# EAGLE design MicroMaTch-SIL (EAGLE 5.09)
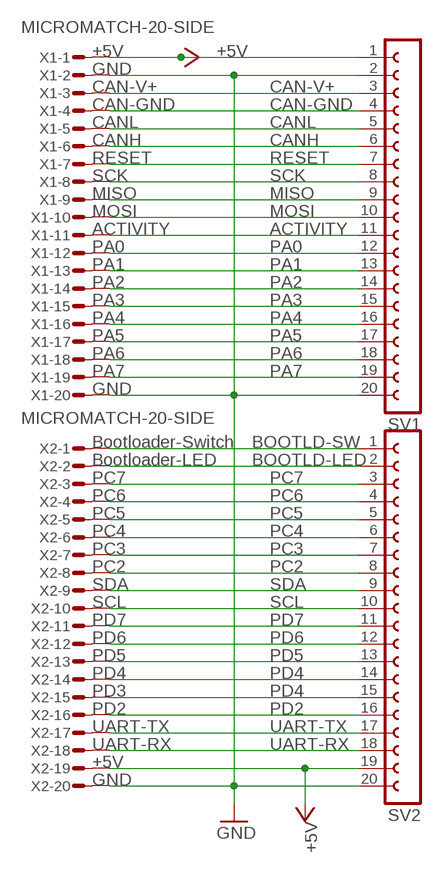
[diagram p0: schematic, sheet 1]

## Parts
SV1  FE20-1  [FE20]
SV2  FE20-1  [FE20]
X1  MICROMATCH-20-SIDE  [MICROMATCH-20-SIDE]
X2  MICROMATCH-20-SIDE  [MICROMATCH-20-SIDE]

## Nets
+5V: SV1.1 SV2.19 X1.1 X2.19
ACTIVITY: SV1.11 X1.11
BOOTLD-LED: SV2.2 X2.2
BOOTLD-SW: SV2.1 X2.1
CAN-GND: SV1.4 X1.4
CAN-V+: SV1.3 X1.3
CANH: SV1.6 X1.6
CANL: SV1.5 X1.5
GND: SV1.2 SV1.20 SV2.20 X1.2 X1.20 X2.20
MISO: SV1.9 X1.9
MOSI: SV1.10 X1.10
PA0: SV1.12 X1.12
PA1: SV1.13 X1.13
PA2: SV1.14 X1.14
PA3: SV1.15 X1.15
PA4: SV1.16 X1.16
PA5: SV1.17 X1.17
PA6: SV1.18 X1.18
PA7: SV1.19 X1.19
PC2: SV2.8 X2.8
PC3: SV2.7 X2.7
PC4: SV2.6 X2.6
PC5: SV2.5 X2.5
PC6: SV2.4 X2.4
PC7: SV2.3 X2.3
PD2: SV2.16 X2.16
PD3: SV2.15 X2.15
PD4: SV2.14 X2.14
PD5: SV2.13 X2.13
PD6: SV2.12 X2.12
PD7: SV2.11 X2.11
RESET: SV1.7 X1.7
SCK: SV1.8 X1.8
SCL: SV2.10 X2.10
SDA: SV2.9 X2.9
UART-RX: SV2.18 X2.18
UART-TX: SV2.17 X2.17

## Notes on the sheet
- +5V
- GND
- CAN-V+
- CAN-GND
- CANL
- CANH
- RESET | RESET
- SCK
- MISO
- MOSI
- ACTIVITY
- PA0
- PA1
- PA2
- PA3
- PA4
- PA5
- PA6
- PA7
- GND
- Bootloader-Switch
- Bootloader-LED
- PC7
- PC6
- PC5
- PC4
- PC3
- PC2
- SDA
- SCL
- PD7
- PD6
- PD5
- PD4
- PD3
- PD2
- UART-TX
- UART-RX
- +5V
- GND

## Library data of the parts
SV1 SV2 = con-lsta:FE20-1: FEMALE HEADER
X1 X2 = apbteam_con-amp-micromatch:MICROMATCH-20: Micro-MaTch 20 Straight connector: Suited for both, female and male.

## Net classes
0 default: width 0.15 mm
1 Power: width 0.5 mm

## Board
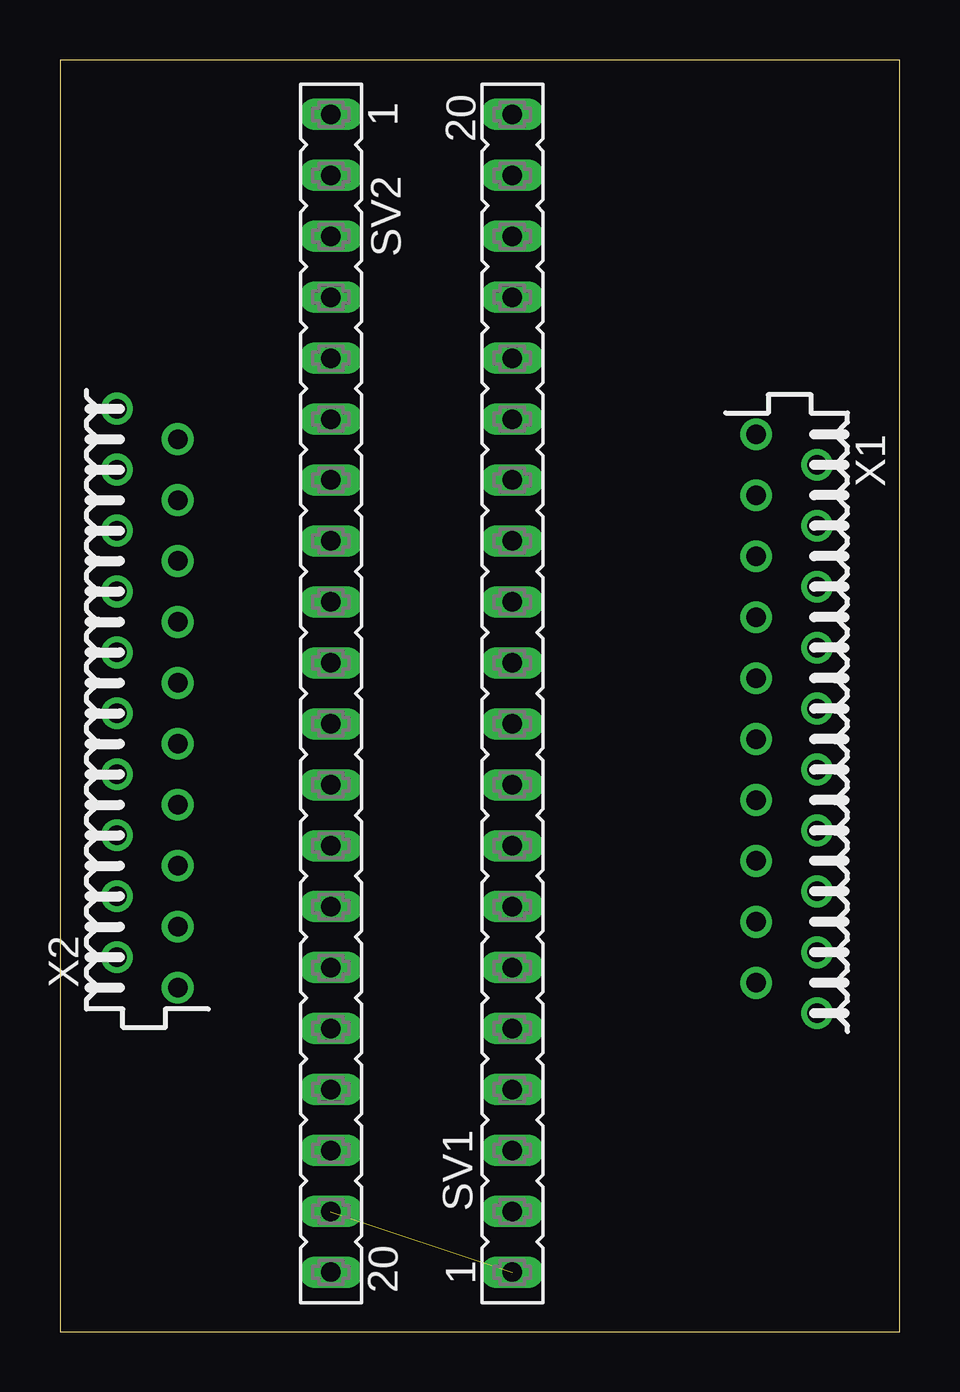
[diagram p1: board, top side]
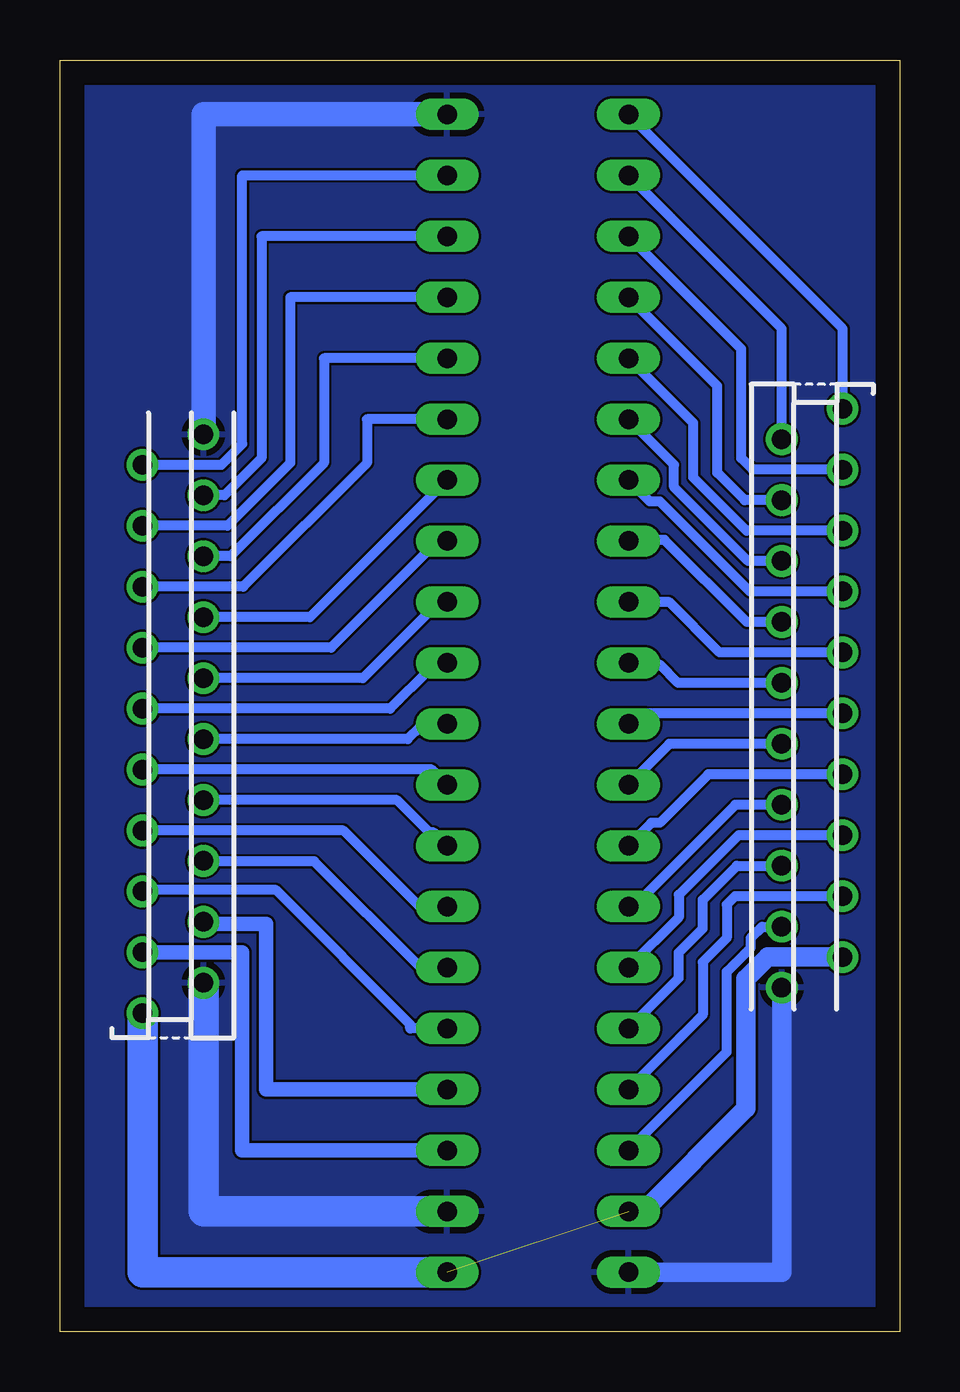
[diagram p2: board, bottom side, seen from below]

Size 35 x 53 mm. Coordinates in mm from the lower left corner, seen from the top.
Outline: 0,0 35,0 35,53 0,53 0,0
Copper layers (1*16): Top 0.035mm / dielectric 1.5mm / Bottom 0.035mm
Design rules "default *": minimum track width 0.2mm, minimum drill 0.2mm, track to track 0.1mm, track to pad 0.1mm, pad to pad 0.1mm, via to via 0.1mm, smd to smd 0.1mm, copper to edge 40mil, drill to drill 8mil, minimum pad ring 10mil, minimum via ring 8mil, stop-mask expansion 4mil, vias tented up to drill 0mil, thermal gap 10mil

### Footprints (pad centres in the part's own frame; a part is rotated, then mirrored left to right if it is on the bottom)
FE20 = drill 0.813 long: 1 -24.13,0; 2 -21.59,0; 3 -19.05,0; 4 -16.51,0; 5 -13.97,0; 6 -11.43,0; 7 -8.89,0; 8 -6.35,0; 9 -3.81,0; 10 -1.27,0; 11 1.27,0; 12 3.81,0; 13 6.35,0; 14 8.89,0; 15 11.43,0; 16 13.97,0; 17 16.51,0; 18 19.05,0; 19 21.59,0; 20 24.13,0
MICROMATCH-20-SIDE = drill 0.813 round: 1 12.065,1.27; 2 10.795,-1.27; 3 9.525,1.27; 4 8.255,-1.27; 5 6.985,1.27; 6 5.715,-1.27; 7 4.445,1.27; 8 3.175,-1.27; 9 1.905,1.27; 10 0.635,-1.27; 11 -0.635,1.27; 12 -1.905,-1.27; 13 -3.175,1.27; 14 -4.445,-1.27; 15 -5.715,1.27; 16 -6.985,-1.27; 17 -8.255,1.27; 18 -9.525,-1.27; 19 -10.795,1.27; 20 -12.065,-1.27

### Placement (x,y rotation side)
SV1  18.86,26.6 90 top
SV2  11.3,26.6 270 top
X1  30.29,25.33 270 top
X2  3.64,26.4 90 top

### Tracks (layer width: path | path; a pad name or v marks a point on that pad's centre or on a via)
+5V  (1 unrouted)
  Bottom 0.813: X2.19 5.5,15.61 6.4,14.7 6.4,9.3 10.7,5 SV2.19
  Bottom 1.27: X1.1 31.56,2.47 SV1.1
ACTIVITY
  Bottom 0.406: X1.11 21.23,25.96 19.6,27.6 19.13,27.6 SV1.11
BOOTLD-LED
  Bottom 0.406: X2.2 4.91,41.8 SV2.2
BOOTLD-SW
  Bottom 0.406: X2.1 2.37,41.8 SV2.1
CAN-GND
  Bottom 0.61: X1.4 29.02,17 26.4,17 26.4,10.09 SV1.4
CAN-V+
  Bottom 0.61: X1.3 27.4,15.8 27.4,7.55 SV1.3
CANH
  Bottom 0.406: X1.6 24.4,19.6 20,15.2 18.89,15.2 SV1.6
CANL
  Bottom 0.406: X1.5 31.56,18.4 26,18.4 20.4,12.8 20.4,12.63 SV1.5
GND
  Bottom 0.813: X2.20 4.91,2.47 SV2.20
  Bottom 1.016: X1.20 29.02,50.73 SV1.20
  Bottom 1.27: X1.2 29.02,5.01 SV1.2
  pour Bottom (isolate 0.1): 0,52.8 0,0 35,0 35,53 0,53
MISO
  Bottom 0.406: X1.9 19.5,23.42 SV1.9
MOSI
  Bottom 0.406: X1.10 20.5,24.7 20,25.2 18.99,25.2 SV1.10
PA0
  Bottom 0.406: X1.12 22.36,27.23 19.4,30.2 19.07,30.2 SV1.12
PA1
  Bottom 0.406: X1.13 23.7,28.5 19.4,32.8 19.01,32.8 SV1.13
PA2
  Bottom 0.406: X1.14 24.57,29.77 SV1.14
PA3
  Bottom 0.406: X1.15 27.36,31.04 22.2,36.2 22.2,38.03 SV1.15
PA4
  Bottom 0.406: X1.16 27.89,32.31 24,36.2 24,40.57 SV1.16
PA5
  Bottom 0.406: X1.17 28.02,33.59 25.4,36.2 25.4,43.11 SV1.17
PA6
  Bottom 0.406: X1.18 28.14,34.85 26.6,36.4 26.6,45.65 SV1.18
PA7
  Bottom 0.406: X1.19 28.27,36.12 27.4,37 27.4,48.19 SV1.19
PC2
  Bottom 0.406: X2.8 6.38,29.57 9.8,33 11.25,33 SV2.8
PC3
  Bottom 0.406: X2.7 6.25,30.84 10,34.6 10.41,34.6 SV2.7
PC4
  Bottom 0.406: X2.6 6.32,32.12 9.4,35.2 9.4,36.13 SV2.6
PC5
  Bottom 0.406: X2.5 6.38,33.38 8.6,35.6 8.6,37.87 SV2.5
PC6
  Bottom 0.406: X2.4 6.46,34.66 7.6,35.8 7.6,39.41 SV2.4
PC7
  Bottom 0.406: SV2.3 6.6,40.95 6.6,36.4 6.12,35.92 X2.3
PD2
  Bottom 0.406: X2.16 6.79,19.41 8.2,18 8.2,16.8 9.2,15.8 9.2,14.73 SV2.16
PD3
  Bottom 0.406: X2.15 6.71,20.68 9.2,18.2 9.2,17.27 SV2.15
PD4
  Bottom 0.406: X2.14 6.84,21.95 10.8,18 11.01,18 SV2.14
PD5
  Bottom 0.406: X2.13 7.97,23.22 10,21.2 10.35,21.2 SV2.13
PD6
  Bottom 0.406: X2.12 9.6,24.49 SV2.12
PD7
  Bottom 0.406: X2.11 10.87,25.76 SV2.11
RESET
  Bottom 0.406: X1.7 23.18,20.88 20,17.7 SV1.7
SCK
  Bottom 0.406: X1.8 20.95,22.15 19.6,20.8 19.41,20.8 SV1.8
SCL
  Bottom 0.406: X2.10 9.23,27.04 10,27.8 11.23,27.8 SV2.10
SDA
  Bottom 0.406: X2.9 7.5,28.3 9.6,30.4 SV2.9
UART-RX
  Bottom 0.406: X2.18 5.72,16.88 6.2,16.4 6.2,16 7.2,15 7.2,11.65 SV2.18
UART-TX
  Bottom 0.406: X2.17 6.86,18.14 7.2,17.8 7.2,16.4 8.2,15.4 8.2,13.19 SV2.17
